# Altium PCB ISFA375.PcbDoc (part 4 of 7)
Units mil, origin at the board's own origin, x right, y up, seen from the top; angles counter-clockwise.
Board outline 5615 x 5520 mil, 6 copper layers (Top_SL, GND, POWER, Signal_Layer, GND2, Bottom_SL), stack 60.472 mil thick; 494 components, 307 nets, 1648 pads, 755 vias.
Unrouted connection lines stored in the file: 315.
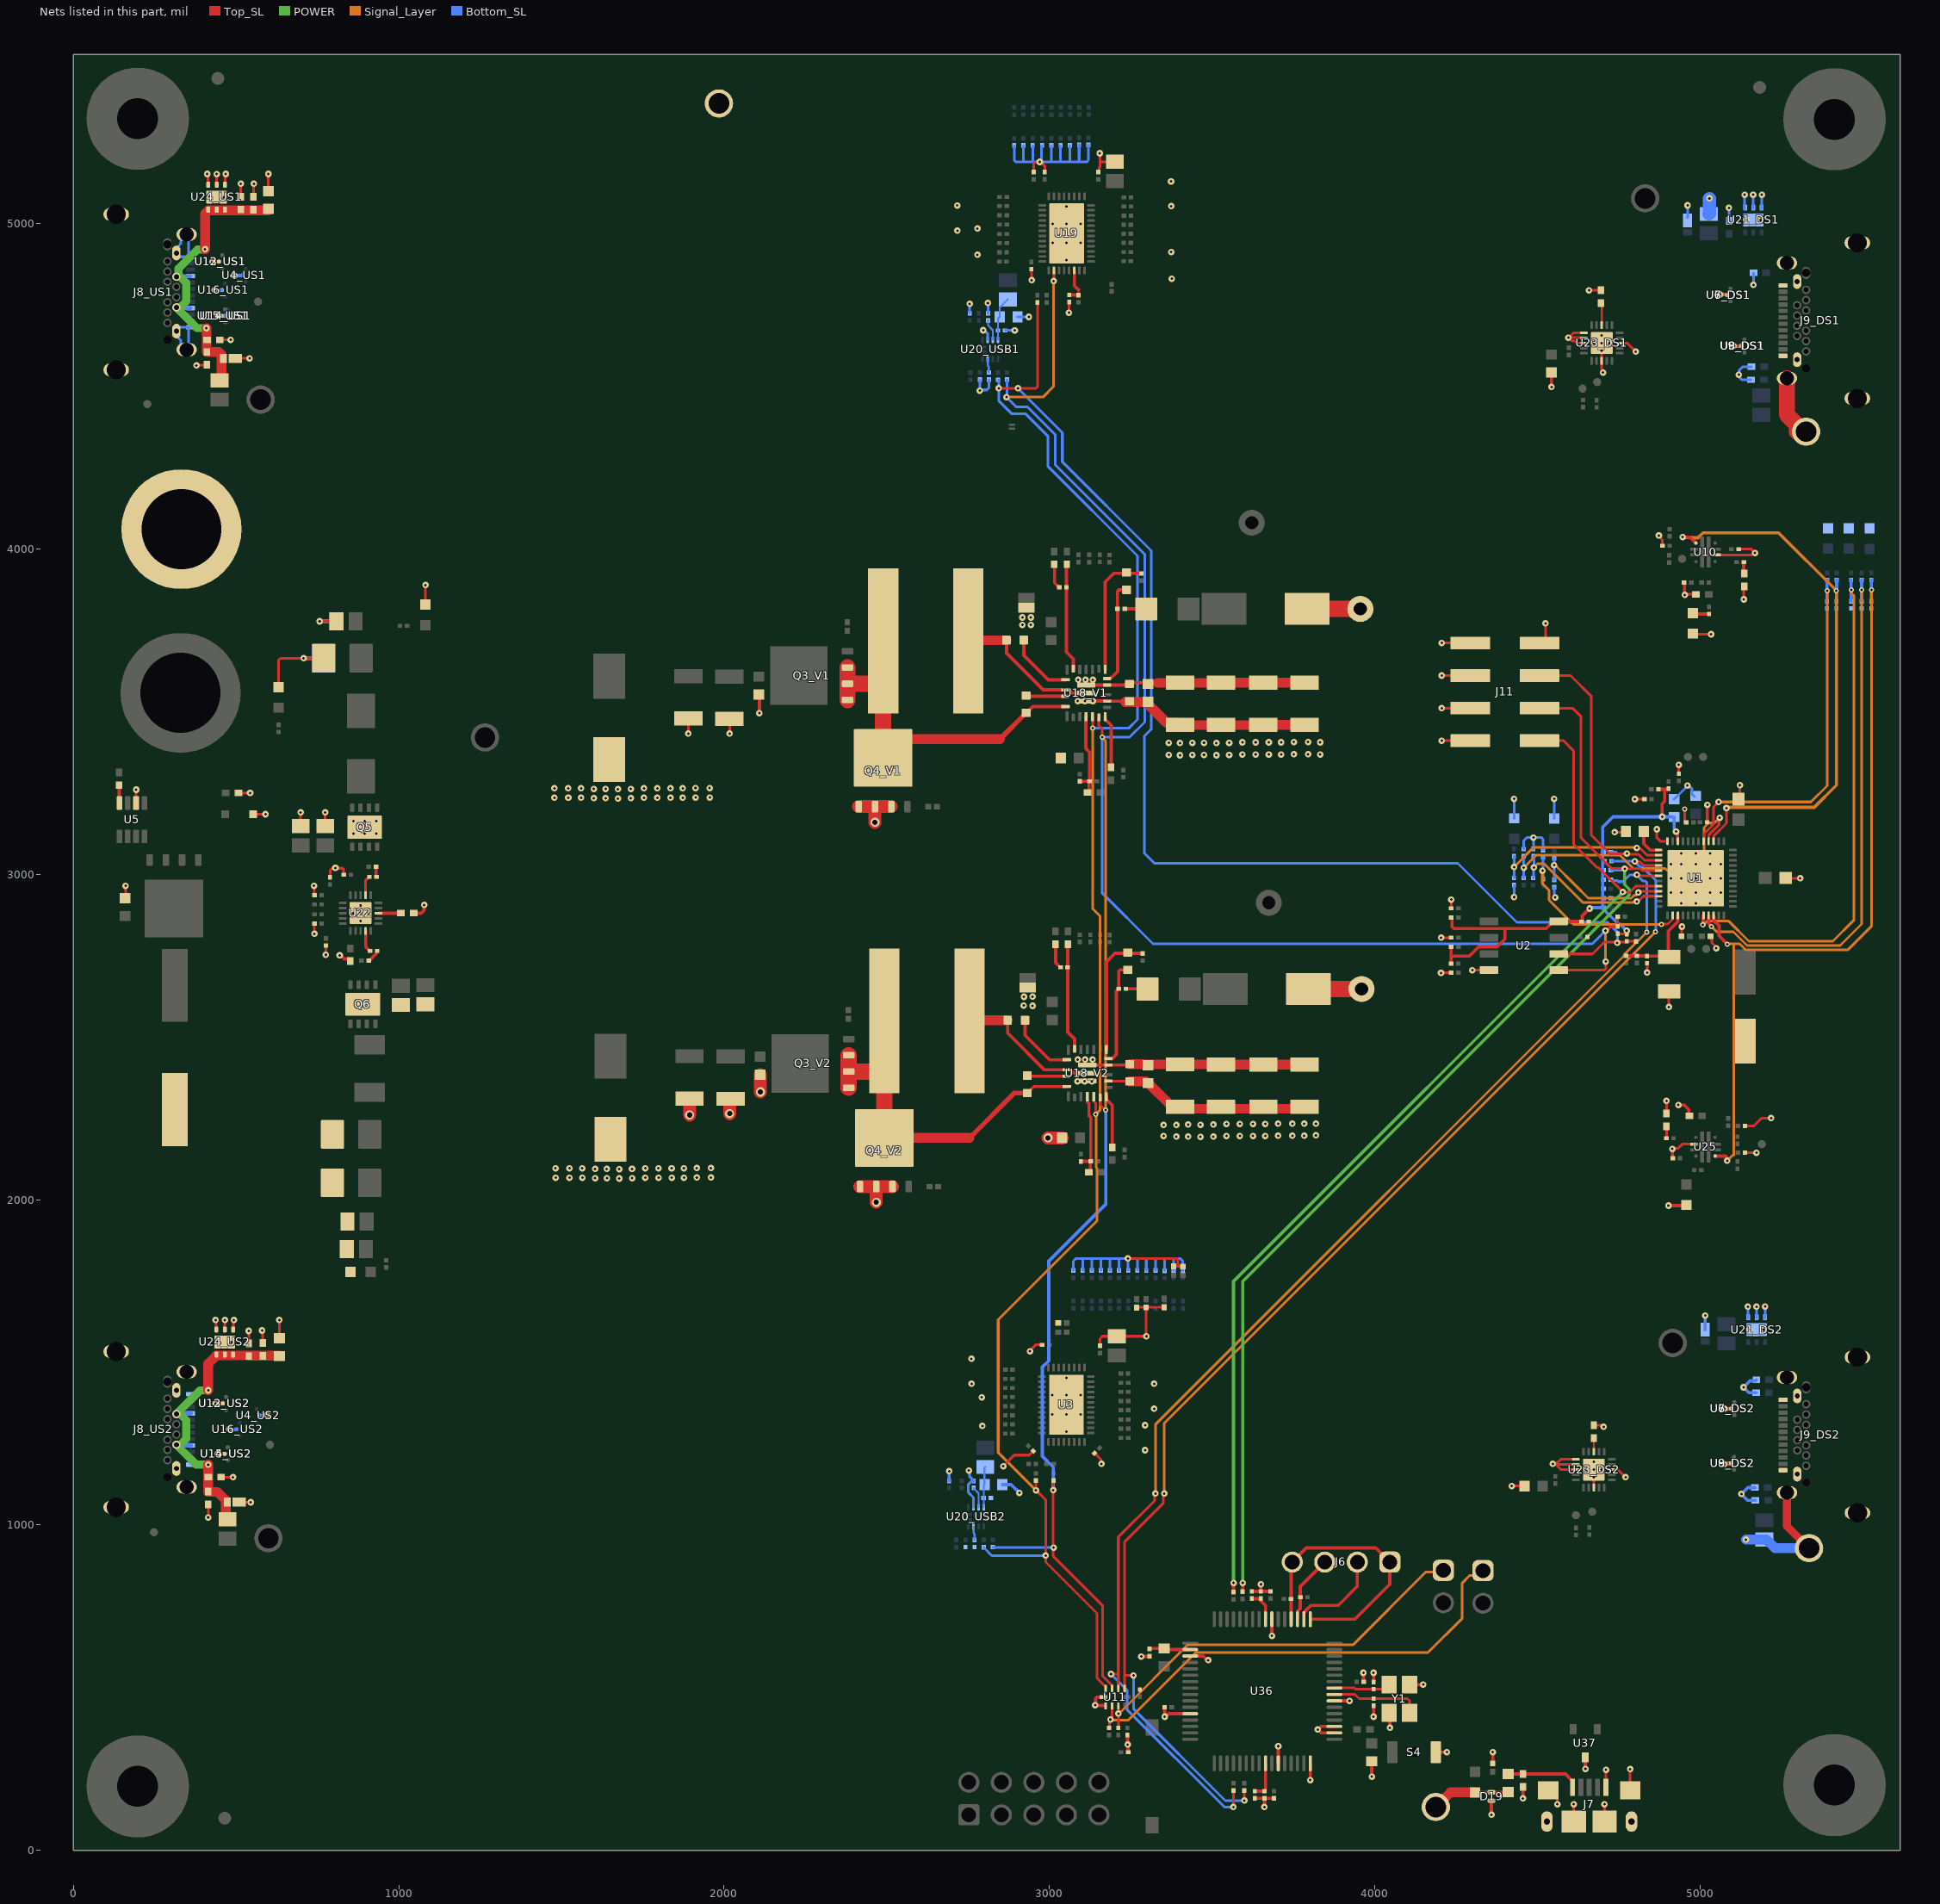
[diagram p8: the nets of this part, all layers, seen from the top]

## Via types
v1: diameter 20, hole 8, Top_SL to Bottom_SL, 628 vias
v2: diameter 19.68, hole 7.87, Top_SL to Bottom_SL, 66 vias
v3: diameter 16, hole 8, Top_SL to Bottom_SL, 23 vias
v4: diameter 16, hole 6, Top_SL to Bottom_SL, tented both sides, 16 vias
v5: diameter 137.8, hole 125.98, Top_SL to Bottom_SL, 8 vias
v6: diameter 50, hole 28, Top_SL to Bottom_SL, 8 vias
v7: diameter 28, hole 16, Top_SL to Bottom_SL, 6 vias

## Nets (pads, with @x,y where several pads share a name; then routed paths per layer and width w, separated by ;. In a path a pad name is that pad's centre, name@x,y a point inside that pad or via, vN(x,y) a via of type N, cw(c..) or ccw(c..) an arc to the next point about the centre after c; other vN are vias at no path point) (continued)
GND: C1.1 C2.1 C3.2 C4.2 C5.2 C6.2 C7.2 C8.1 C9.1 C10.2 C11.2 C12.2 C13.2 C14.2 C15.2 C16.2 C17.2 C20.2 C23.2 C36.2 C37.1 C40_V1.2 C40_V2.2 C41_V1.2 C41_V2.2 C42_V1.2 C42_V2.2 C43_V1.2 C43_V2.2 C45_V1.2 C45_V2.2 C47_V1.2 C47_V2.2 C48_V1.2 C48_V2.2 C49_V1.2 C49_V2.2 C50_V1.2 C50_V2.2 C51_V1.2 C51_V2.2 C52_V1.2 C52_V2.2 C59.2 C60.2 C61.2 C62.2 C63.2 C65.2 C66.2 C80_V1.1 C80_V2.1 C82_USB1.2 C82_USB2.2 C83_USB1.2 C83_USB2.2 C84.1 C85_USB1.2 C85_USB2.2 C86.2 C88_DS1.1 C88_DS2.1 C90.2 C91.2 C92.2 C93.2 C94.2 C95.2 C96.2 C97.2 C98.2 C99.2 C100_USB1.2 C100_USB2.2 C101.2 C102.2 C103.2 C105.2 C106.2 C107.2 C108.2 C109_US1.2 C109_US2.2 C110.2 C111_US1.2 C111_US2.2 C112.2 C113.2 C114.2 C115.1 C116.2 C118_DS1.2 C118_DS2.2 C119_DS1.2 C119_DS2.2 C120_DS1.2 C120_DS2.2 C121_DS1.2 C121_DS2.2 C122_DS1.2 C122_DS2.2 C123_DS1.1 C123_DS2.1 C124_US1.2 C124_US2.2 C125_US1.2 C125_US2.2 C126_US1.2 C126_US2.2 C127.2 C128.2 C129.1 C130.1 C131.1 D1.1 D2.1 D9.1 D10.1 D11.1 D12.1 D13_DS1.2 D13_DS2.2 D14_US1.2 D14_US2.2 D15.1 D16.1 D17.1 D18.1 D19.1 D21.1 J7.5 J7.6 J7.7 J7.8 J7.9 J7.10 J7.11 J8_US1.1 J8_US1.2 J8_US1.3 J8_US1.4 J8_US1.A1 J8_US1.A12 J8_US1.B1 J8_US1.B12 J8_US2.1 J8_US2.2 J8_US2.3 J8_US2.4 J8_US2.A1 J8_US2.A12 J8_US2.B1 J8_US2.B12 J9_DS1.1 J9_DS1.2 J9_DS1.3 J9_DS1.4 J9_DS1.A1 J9_DS1.A12 J9_DS1.B1 J9_DS1.B12 J9_DS2.1 J9_DS2.2 J9_DS2.3 J9_DS2.4 J9_DS2.A1 J9_DS2.A12 J9_DS2.B1 J9_DS2.B12 J11.2 J11.4 J11.6 J11.7 J11.8 J15.1 NT1_V1.1 NT1_V2.1 Q4_V1.1 Q4_V1.2 Q4_V1.3 Q4_V2.1 Q4_V2.2 Q4_V2.3 Q5.9@895.11,3145.01 Q6.9@889.16,2600.69 R12.1 R20.1 R21.1 R24.1 R25.1 R26.1 R27.1 R28.1 R31.2 R32.2 R51.1 R52.1 R53.1 R54.1 R55.1 R56.1 R57.1 R58.1 R59.1 R60.1 R61.1 R64.1 R91_USB1.2 R91_USB2.2 R92.2 R93.1 R94.1 R95.1 R96.1 R97.1 R98.1 R99.1 R100.1 R101.1 R102.2 R104_USB1.1 R104_USB2.1 R107.2 R111.1 R112.1 R113.1 R123.1 R124.1 R130.2 R131.2 R132.2 R134.1 R136.2 R137.2 R138.2 R139.1 R161.1 R162.1 R165.2 R167.1 R170.2 R171.1 S4.1 TP6.1 TP8_V1.1 TP8_V2.1 TP11_DS1.1 TP11_DS2.1 U1.36 U1.49 U2.4 U3.41 U4_US1.1@519.08,4841 U4_US2.1@572.72,1336.58 U5.2 U6_DS1.1@5083.33,4781.01 U6_DS2.1@5095.54,1357.5 U7_DS1.1@5083.42,4780.98 U7_DS2.1@5096.08,1358 U8_DS1.1@5126.91,4624.27 U8_DS2.1@5095.08,1190 U9_DS1.1@5126.61,4623.98 U9_DS2.1@5095.08,1190 U10.8 U11.5 U11.6 U12_US1.1@447.16,4883.32 U12_US2.1@459.08,1374 U13_US1.1@447.16,4883.32 U13_US2.1@459.06,1373.75 U14_US1.1@463.62,4716.48 U14_US2.1@463.98,1218.66 U15_US1.1@455.59,4717.18 U15_US2.1@465.08,1219 U16_US1.1@456,4796 U16_US2.1@500.63,1294 U18_V1.9 U18_V1.24 U18_V2.9 U18_V2.24 U19.41 U20_USB1.10 U20_USB2.10 U21_DS1.1 U21_DS1.2 U21_DS1.3 U21_DS1.7@5164,5011.61 U21_DS2.1 U21_DS2.2 U21_DS2.3 U21_DS2.7@5174,1600.61 U22.21@882.47,2880.95 U23_DS1.6 U23_DS1.7 U23_DS1.8 U23_DS1.13 U23_DS1.18 U23_DS1.21@4697.97,4633.37 U23_DS2.6 U23_DS2.7 U23_DS2.8 U23_DS2.13 U23_DS2.18 U23_DS2.21@4673.68,1170.32 U24_US1.1 U24_US1.2 U24_US1.3 U24_US1.7@440,5081.61 U24_US2.1 U24_US2.2 U24_US2.3 U24_US2.7@465,1562.61 U25.8 U36.3 U36.12 U36.27 U36.32 U36.34 U36.35 U36.39 U36.55 U37.3 Y1.2 Y1.4 | length 13672.6
  Top_SL w8: C103.2@158.92,2927.2 159.89,2928.17 v1(159.89,2965.02) ; U5.2@192.39,3219.42 v1(192.39,3260.5) ; v1(377.62,4564.47) 378.6,4565.46 409.32,4565.46 C124_US1.2@410.3,4566.44 ; v1(411,5153) 412.7,5151.3 412.7,5121.7 U24_US1.3@414.41,5120 ; v1(413.9,1023.38) 414.15,1023.62 414.15,1063.38 C124_US2.2@414.39,1063.62 ; v1(426.63,4882.57) U13_US1.1@446.6,4882.57 ; v1(437,1630) 438.2,1628.8 438.2,1599.41 U24_US2.3@439.44,1598.17 ; U24_US1.2@440,5120 v1@440,5152.78 ; v1(441.47,4718.12) 441.94,4717.65 455.12,4717.65 U15_US1.1@455.59,4717.18 ; C111_US1.2@449.69,4643 449.86,4643.17 482.65,4643.17 v1(482.82,4643.35) ; C111_US2.2@453.69,1147 453.86,1147.17 490.45,1147.17 v1(490.63,1147.35) ; U24_US2.2@465.03,1598.17 v1(465.03,1630.17) ; U24_US1.1@465.59,5117.77 466.8,5118.98 466.8,5151.8 v1(468,5153) ; U24_US2.1@490.63,1598.17 491.8,1599.34 491.8,1628.8 v1(493,1630) ; D14_US1.2@498.7,4586.13 v1(541.19,4586.13) ; D14_US2.2@503.52,1070 v1(544.38,1070) ; C102.2@506.69,3250 v1(543,3250) ; C126_US1.2@514,5083.32 v1(514,5122.95) ; C126_US2.2@538.77,1563.86 v1(538.77,1596.75) ; D9.1@552.31,3185.39 552.5,3185.19 589.81,3185.19 v1(590,3185) ; C125_US1.2@553,5082.69 553.89,5083.58 553.89,5122.06 v1(554.79,5122.95) ; v1(579.83,1598.17) 580.91,1597.09 580.91,1560.77 C125_US2.2@582,1559.69 ; C109_US1.2@599,5100.56 v1(599,5153) ; D10.1@630,3575.46 630,3657.88 636.5,3664.38 v1(707.49,3664.38) ; v1(632.77,1630.17) 632.77,1574.79 C109_US2.2@633,1574.56 ; v1(698.11,3190.47) 698.11,3148.84 C66.2@698.61,3148.34 ; v1(739.21,2965.02) 739.94,2964.29 739.94,2936.8 R112.1@740.68,2936.06 ; R111.1@740.59,2849.03 R111.1@740.59,2849.03 740.63,2817.49 v1(740.68,2817.45) ; C90.2@768.5,3664.38 C90.2@769.12,3665 ; v1(773.59,3190.47) 773.59,3148.5 C65.2@773.75,3148.34 ; v1(775.83,2752.88) R113.1@775.83,2781.15 ; R28.1@788.77,2991.22 788.77,3011.8 794.66,3017.69 802.77,3017.69 v1(805.07,3019.99) 806.14,3018.92 827.07,3018.92 830.69,3015.3 R24.1@830.69,2999.09 ; D11.1@1082.02,3829.18 1082.21,3829.37 v1(1082.21,3889.38) ; v1(1890.13,3432.62) C40_V1.2@1890.13,3479.21 ; C41_V1.2@2016.13,3478.21 2017.13,3477.21 v1(2017.13,3432.62) ; v1(2857.88,1181.02) 2891.81,1214.95 2937.6,1214.95 2950.29,1227.64 C16.2@2950.79,1227.64 ; v1(2940.42,1534.01) 2940.42,1536.9 2957.36,1553.84 C14.2@2977.7,1553.84 ; C62.2@2944.65,4860.67 2944.94,4860.38 2944.94,4826.92 v1(2945.24,4826.62) ; C60.2@2951.5,5158.71 2951.5,5185.28 2954.45,5188.23 2968.5,5188.23 v1(2970.31,5190.04) ; v1@2971.16,5188.23 2973.46,5190.53 2973.46,5189.97 2985.63,5177.8 C61.2@2985.63,5158.71 ; v1(3059.73,4726.4) 3060.28,4726.96 3060.28,4758.59 C84.1@3060.84,4759.15 ; C17.2@3138.85,1221.29 3157.71,1202.43 3157.71,1190.2 v1(3160.01,1187.9) ; C63.2@3150.01,5158.71 3152.31,5161.01 3152.31,5171.3 3155.73,5174.72 3155.73,5190.53 ; v1(3154.38,5216.65) 3155.73,5215.3 3155.73,5190.53 ; C15.2@3155.61,1550.69 3155.61,1573 3162.83,1580.22 C13.2@3207.1,1580.22 v1(3298.14,1580.22) 3297.57,1580.79 3297.57,1668.44 R60.1@3297,1669.01 ; U18_V2.9@3181.12,2364.75 3181.78,2364.09 C80_V2.1@3246.34,2364.09 ; C59.2@3201.31,5190.53 3155.73,5190.53 ; v1(3241.08,1819.49) 3391.81,1819.49 3394.54,1816.76 3394.54,1795.15 ; R54.1@3268.21,1668.5 3268.96,1669.25 3352.25,1669.25 R56.1@3353,1670.01 ; R59.1@3382.07,1795.7 3382.61,1795.15 3394.54,1795.15 ; R57.1@3410.14,1794.61 3409.6,1795.15 3394.54,1795.15 ; v1(4203.78,2696.83) 4204.3,2697.35 4234.46,2697.35 R27.1@4234.98,2697.87 ; v1(4204,2805.51) R26.1@4235.19,2805.52 ; v1(4205.91,3411.17) J11.2@4293.85,3411.17 ; v1(4205.91,3511.17) J11.4@4293.85,3511.17 ; v1(4205.91,3611.17) J11.6@4293.85,3611.17 ; v1(4205.91,3711.17) J11.8@4293.85,3711.17 ; R25.1@4235.19,2895.57 v1(4235.19,2922.43) ; v1(4300.25,2705.52) U2.4@4350.93,2705.52 ; v1(4420.99,1119.81) C122_DS2.2@4460.77,1119.81 ; J11.7@4506.44,3711.17 4509.1,3711.17 4524.79,3726.85 v1(4524.79,3771.62) ; J7.8@4533.33,185 4537.27,185 4560.83,161.45 4560.83,142.34 v1(4561.47,141.7) ; v1(4547.78,1188.19) 4549.84,1186.13 v1@4557.03,1186.13 ; v1@4554.97,1188.19 4558.22,1188.19 4571.84,1201.82 U23_DS2.6@4618.56,1201.82 ; v1(4595.31,4649.73) 4637.93,4649.73 4637.93,4649.6 4638.41,4649.12 U23_DS1.7@4642.85,4649.12 ; v1@4599.23,4645.81 4599.35,4645.93 4606,4639.28 4615.65,4639.28 4621.55,4633.37 U23_DS1.8@4642.85,4633.37 ; v1@4599.65,4650.39 4599.65,4653.23 4611.29,4664.87 U23_DS1.6@4642.85,4664.87 ; J7.10@4612.06,88.56 v1(4612.06,141.7) ; U23_DS2.8@4618.56,1170.32 4572.84,1170.32 v1@4557.03,1186.13 ; U23_DS2.7@4618.56,1186.07 4618.5,1186.13 v1@4557.03,1186.13 ; v1(4658.88,4795.28) v1(4658.88,4795.28) 4695.94,4795.33 C123_DS1.1@4696,4795.39 ; U23_DS2.13@4673.68,1115.2 v2(4673.68,1146.7) ; C123_DS2.1@4673.68,1306.95 4674.16,1307.43 4694.88,1307.43 4700.56,1301.75 v1(4703.81,1301.75) ; v2(4697.97,4609.75) U23_DS1.13@4697.97,4578.25 4697.97,4552.83 4699.29,4551.51 4699.29,4544.91 v1(4701.58,4542.62) ; J7.11@4706.56,88.55 v1(4706.56,141.7) ; J7.5@4710.5,193.86 4710.75,194.11 4710.75,247.75 v1(4711,248) ; U23_DS2.18@4728.8,1170.32 4747.89,1170.32 v1(4771.23,1146.98) ; v1(4737.66,3130) 4770.3,3130 C9.1@4772.34,3132.03 ; U23_DS1.18@4753.09,4633.37 4775.82,4633.37 v1(4802.39,4606.8) ; v1(4785,250) 4785,185.31 J7.9@4785.3,185 ; v1(4799.91,3231.26) 4800.06,3231.41 4828.69,3231.41 R21.1@4828.84,3231.56 ; R132.2@4837.31,2726.96 4837.49,2726.78 4837.49,2698.22 v1(4837.67,2698.04) ; v1(4867.5,3138.63) 4867.5,3112.72 4878.05,3102.17 U1.36@4900.39,3102.17 ; v1(4873.45,4041.64) 4873.45,4039.22 4884.27,4028.4 4884.27,4012.4 4884.55,4012.11 R107.2@4884.55,4010.1 ; v1(4896.83,2304) 4897.17,2303.66 C131.1@4897.17,2264.63 ; v1(4904.35,2592.59) 4904.35,2639.85 C129.1@4904.75,2640.25 ; v1(4914.75,2156.09) 4917.05,2158.39 4932.81,2158.39 4945.28,2170.86 U25.8@4981.41,2170.86 ; R12.1@4934.92,3309.24 v1(4934.92,3337) ; C6.2@4943.02,2810 4943.95,2810.93 4943.95,2838.66 v1(4944.88,2839.59) ; R64.1@4951.31,3896.96 4952.23,3896.03 4952.23,3860.17 v1(4953.16,3859.24) ; v1@4951.4,3861 C3.2@4987.85,3861 ; v3(4952.95,3201.2) 4953.06,3201.1 4953.06,3160.73 C1.1@4953.16,3160.63 ; D1.1@4978.29,3740.13 4980.26,3738.16 v1(5033.98,3738.16) ; C2.1@5021.92,3160.63 5022.38,3161.09 5022.38,3213.32 v1(5022.84,3213.78) ; C7.2@5031.99,2810 5032.25,2810 5036.51,2805.73 5036.51,2789.73 5050,2776.25 v1(5050,2773) ; U10.8@5052.36,3982.05 5159.98,3982.05 5165.93,3988 v1(5169.18,3988) 5157.41,3999.76 R139.1@5118.7,3999.76 ; C86.2@5117.26,3213.78 5118.51,3215.03 5118.51,3241.08 5122.44,3245.01 v1(5122.44,3274.3) ; C130.1@5133.4,3883.22 5134.13,3882.5 5134.13,3846.18 v1(5134.85,3845.45) ; R170.2@5138.1,2144.45 v1(5173.61,2144.45) ; R167.1@5138.28,2226.45 5141.17,2226.45 5141.37,2226.24 5164.78,2226.24 5189.38,2250.85 v1(5218.47,2250.85) ; C11.2@5263.36,2988.87 5264.23,2988 v1(5308,2988)
  Top_SL w10: v1(436.72,1373.75) U13_US2.1@459.06,1373.75 ; v1(442.84,1219.18) 442.93,1219.09 464.99,1219.09 U15_US2.1@465.08,1219 ; v1(707.49,3664.38) C90.2@768.5,3664.38 ; v1(756.75,3778) C95.2@808.01,3778 ; v1(818.3,2751.31) 821,2751.31 832.3,2740.01 845.73,2740.01 850.57,2735.17 C98.2@850.57,2733.2 ; C99.2@1045.98,2880.95 1069.22,2880.95 1077.75,2889.47 v1(1077.75,2906.22) ; C42_V1.2@2107.13,3552.61 2108.53,3551.21 v1(2108.53,3495.76) ; U18_V1.24@3112.86,3532.75 3132.83,3532.75 v1(3133.08,3533) 3133.33,3532.75 U18_V1.9@3177.33,3532.75 ; U11.5@3166.57,470.96 3146.27,470.96 3142.32,467.01 3142.32,448.39 v1(3140.41,446.48) 3141.46,445.43 3171.43,445.43 U11.6@3172.48,444.38 ; U18_V1.9@3184.63,3532.67 3230.39,3532.67 ; R162.1@3239.85,354.55 3240.24,354.15 3240.24,325.89 v1(3240.64,325.5) 3241.37,324.76 3241.37,302.29 R161.1@3242.11,301.56 ; v1(3282.12,595.77) 3282.81,596.46 3306.95,596.46 C37.1@3307.64,597.15 ; C107.2@3354.27,439.98 v1(3354.27,410.87) 3356.98,410.87 3366.41,420.3 U36.12@3432.9,420.3 ; U36.3@3432.9,597.46 3472.51,597.46 3485.42,584.55 v1(3488,584.55) ; C110.2@3622,796.02 3622.07,795.95 C128.2@3650.03,795.95 ; C108.2@3631.33,160.03 C127.2@3660.86,160.03 ; C128.2@3650.03,795.89 C128.2@3650.03,795.95 ; v1(3650.03,817.9) C128.2@3650.03,795.95 ; v1(3660.86,133.36) C127.2@3660.86,160.03 ; C105.2@3679.56,795.89 3679.49,795.95 C128.2@3650.03,795.95 ; v1(3683.89,659.45) U36.55@3683.89,710.65 ; C106.2@3690.21,159.23 C106.2@3690.21,160.02 ; C106.2@3690.21,160.02 C127.2@3660.86,160.03 ; U36.27@3703.57,267.74 v1(3703.57,320.26) ; v1(3802,215.74) U36.32@3802,267.74 ; v1(3824.85,371.66) v1@3825.79,371.66 ; U36.34@3875.82,361.24 3836.21,361.24 v1@3825.79,371.66 ; U36.35@3875.82,380.93 3836.21,380.93 3826.94,371.66 v1@3825.79,371.66 ; U36.39@3875.82,459.67 v1@3922.55,459.69 ; v1(3965.32,545.89) 3965.88,545.32 3965.88,518.88 C36.2@3966.44,518.32 C36.2@3966.25,518.12 ; v1(3990.85,226.65) C112.2@3990.85,274 ; v1@3996.5,410.87 C113.2@3996.52,444.31 ; C114.2@3996.52,517.67 v1(3996.45,545.89) ; Y1.4@4044.5,423.05 4046.48,421.07 v1(4046.48,376.64) ; Y1.2@4107.5,509.67 v1(4149,509.67) ; S4.1@4187.94,301.56 4188.38,302 v1(4222,302) ; v1(4358.86,109.26) D19.1@4358.86,153.04 ; R134.1@4362.92,267.31 4363.04,267.44 4363.04,301.88 v1(4363.17,302) ; v1(4455.86,159.83) C115.1@4455.86,195.15 ; v1(4543.49,4498.34) C122_DS1.2@4543.49,4542.62 ; U37.3@4647.1,285.81 4647.46,285.45 4647.46,250.9 v1(4647.82,250.54) ; v1(4902.75,1981.92) 4955.99,1981.92 D2.1@4957.96,1983.89 ; v1(4914.75,2156.09) 4915.44,2155.41 4915.44,2128.24 R171.1@4916.13,2127.55 ; v1(4933.62,2291) 4951.71,2291 4965.6,2277.12 4965.6,2259.62 C5.2@4967.08,2258.13 ; v1(5061.44,4782.41) 5062.14,4781.71 5082.63,4781.71 U6_DS1.1@5083.33,4781.01 ; v1(5074,1187.07) 5076.71,1187.07 5078.73,1189.09 5094.17,1189.09 U8_DS2.1@5095.08,1190 ; v1(5074.66,1357.63) 5095.42,1357.63 U6_DS2.1@5095.54,1357.5 ; v1(5103.55,4623.98) 5103.69,4624.12 5126.76,4624.12 U8_DS1.1@5126.91,4624.27
  Top_SL w25: J9_DS2.1@5267.46,1099.6 5267.46,996.57 TP11_DS2.1@5335.13,928.9
  Top_SL w30: C80_V1.1@3233.42,3529.8 3296.63,3529.8 3360.11,3466.32 3394.18,3466.32 3401.58,3458.92 C50_V1.2@3657.47,3458.92 ; C80_V2.1@3247,2363.43 3297.03,2363.43 3302.02,2358.44 3303.98,2358.44 3369.72,2292.7 3394.98,2292.7 3407.82,2279.87 3521.75,2279.87 C49_V2.2@3527.65,2285.77 3533.66,2279.77 3651.63,2279.77 C50_V2.2@3657.53,2285.67 3663.44,2279.77 3778.63,2279.77 C51_V2.2@3784.53,2285.67 ; C50_V1.2@3657.47,3459.29 C51_V1.2@3784.47,3459.29
  Top_SL w40: v7(1893.91,2260.48) C40_V2.2@1893.91,2311.21 ; v7(2017.13,2264.62) 2017.13,2308.55 2018.78,2310.21 C41_V2.2@2019.91,2310.21 ; C42_V2.2@2110.91,2384.61 2110.91,2332.03 v7(2111.66,2331.28) ; Q4_V1.1@2413.83,3208.4 Q4_V1.2@2463.83,3208.4 ; Q4_V2.1@2417.62,2040.4 Q4_V2.2@2467.62,2040.4 ; v7(2463.83,3160.17) Q4_V1.2@2463.83,3208.4 ; v7(2467.62,1992.17) Q4_V2.2@2467.62,2040.4 ; Q4_V1.3@2513.83,3208.4 Q4_V1.2@2463.83,3208.4 ; Q4_V2.3@2517.62,2040.4 Q4_V2.2@2467.62,2040.4 ; v7(2995.91,2190.01) C45_V2.2@3038.83,2190.01
  Top_SL w50: J15.1@331.92,4061.16 J15.1@418.26,4061.16 ; C52_V1.2@3792.69,3815.9 TP8_V1.1@3955.74,3815.9 ; C52_V2.2@3796.48,2647.9 TP8_V2.1@3959.53,2647.9 ; J9_DS1.1@5267.11,4525.1 5267.11,4412.71 5298.01,4381.81 TP11_DS1.1@5298.01,4360.98
  Bottom_SL w8: J8_US1.A1@359.92,4681.73 J8_US1.A1@356.71,4681.73 ; J8_US1.A12@359.92,4898.27 J8_US1.A12@356.71,4898.27 ; v1(426.63,4882.57) U12_US1.1@446.41,4882.57 ; v1(434,4795.9) 434.05,4795.95 455.95,4795.95 U16_US1.1@456,4796 ; v1(441.47,4718.12) 442.29,4717.3 462.8,4717.3 U14_US1.1@463.42,4716.69 ; v1(2752.24,1167.42) 2754.15,1165.51 2754.15,1149.86 2767.27,1136.74 C100_USB2.2@2767.27,1135.95 2767.27,1135.16 2765.97,1133.86 2759.71,1133.86 2750.97,1125.13 2750.97,1100.06 2766.56,1084.48 U20_USB2.10@2766.56,1054.57 ; R104_USB1.1@2755,4725.02 v1(2755,4753.49) ; v1(2785.81,4487) v1@2785.9,4487.1 ; R91_USB1.2@2786,4520.98 2785.9,4520.88 v1@2785.9,4487.1 ; v1(2796.43,4672.57) 2799.68,4672.57 2808.51,4663.74 2810.55,4663.74 U20_USB1.10@2810.55,4643.27 ; v1(2810.82,4756.6) 2811.04,4756.38 2811.04,4724.87 C100_USB1.2@2811.27,4724.65 ; C85_USB1.2@2814,4520.98 2814,4495.7 2807.6,4489.3 2788.1,4489.3 v1@2785.9,4487.1 ; C82_USB1.2@2864.02,4672 v1(2893.5,4672) ; R94.1@2891.67,5240.65 2891.67,5195.21 2896.36,5190.53 2919.24,5190.53 ; C83_USB1.2@2902.11,4713.62 v1(2936.93,4713.62) ; R101.1@2920.21,5240.65 2920.21,5191.49 2919.24,5190.53 ; R99.1@2948.74,5240.65 2948.74,5191.21 2948.06,5190.53 ; v1(2970.31,5190.04) 2969.82,5190.53 2948.06,5190.53 ; R93.1@2977.28,5240.64 2975.37,5238.73 2975.37,5192.44 2973.46,5190.53 3003.9,5190.53 ; R100.1@3005.81,5240.64 3005.81,5192.44 3003.9,5190.53 ; R96.1@3034.35,5240.64 3034.35,5190.53 ; R98.1@3062.88,5240.64 3062.88,5190.53 ; R53.1@3073.26,1782.44 3073.26,1810.96 3081.78,1819.49 3213.63,1819.49 ; R95.1@3091.42,5242.64 3091.42,5190.53 ; R52.1@3102.14,1782.62 3102.45,1782.92 3102.45,1819.49 ; R97.1@3119.95,5242.64 3119.95,5195.21 3115.27,5190.53 3091.42,5190.53 ; R124.1@3130.14,1782.44 3130.14,1819.49 ; R61.1@3158.14,1782.62 3158.14,1819.49 ; R58.1@3186.14,1782.63 3186.14,1819.49 ; R51.1@3214.11,1782.72 3214.11,1819.01 3213.63,1819.49 ; R55.1@3242.14,1782.89 v1@3242.11,1810.96 ; R54.1@3270.14,1782.89 3270.14,1819.49 ; R60.1@3298.14,1781.89 3297.85,1782.18 3297.85,1819.49 ; R123.1@3326.14,1782.62 3326.14,1819.49 ; R56.1@3354.14,1781.62 3354.14,1819.49 ; R59.1@3382.14,1782.63 3382.07,1782.71 3382.07,1819.49 ; R57.1@3410.14,1781.62 3410.14,1810.96 3401.62,1819.49 3382.07,1819.49 ; v1(4428.35,2930.21) R32.2@4428.35,2966.99 ; D16.1@4428.35,3172.38 v1(4428.35,3232.01) ; R102.2@4458.22,3077.65 4458.22,3104.36 4467,3113.14 v1(4488.14,3113.14) ; R131.2@4487.98,3078.2 4488.06,3078.28 v1(4488.14,3113.14) v1(4488.14,3113.14) ; R130.2@4517.7,3074.87 4517.7,3107.91 4512.48,3113.14 v1(4488.14,3113.14) ; v1(4551.57,3232.01) 4551.57,3172.69 D15.1@4552,3172.26 ; R31.2@4552,2961.03 4552,2935.25 4555,2932.25 v1(4555,2929) ; C8.1@4920.5,3231.56 4932.25,3243.31 4933.23,3243.31 4961.02,3271.1 v1(4961.02,3273.06) ; D13_DS1.2@4961.04,5018.82 4962,5019.78 v1(4962,5056.5) ; v1@4965,3273.06 4975.81,3262.25 4975.81,3246.14 C4.2@4982.76,3239.19 ; v1(5088.96,5048.72) 5089.59,5048.09 5089.59,5008.9 C119_DS1.2@5090.22,5008.27 ; v1(5137,5089) 5137.41,5088.59 5137.41,5046.18 U21_DS1.1@5137.82,5045.77 ; v1(5147.32,1671.05) 5147.66,1670.7 5147.66,1636.11 U21_DS2.1@5148,1635.77 ; C120_DS1.2@5156.52,4520.5 5128.49,4520.5 5121.53,4527.46 5121.53,4533.43 v1(5119.23,4535.73) 5120.43,4536.93 5120.43,4549.64 5131.3,4560.51 C121_DS1.2@5158.25,4560.51 ; U21_DS1.2@5163.41,5045.77 v1(5163.41,5089) ; v1(5164.16,4812.18) C118_DS1.2@5164.16,4848.92 ; U21_DS2.2@5173.6,1635.78 v1(5173.61,1671.05) ; U21_DS1.3@5189,5045.77 5189.5,5046.27 5189.5,5088.5 v1(5190,5089) ; U21_DS2.3@5199.25,1635.84 5199.8,1636.39 5199.8,1671.8 v1(5200,1672) ; J8_US1.A1@356.71,4681.73 324.35,4681.73 316.22,4673.61 J8_US1.B12@316.22,4669.92 316.22,4655.32 329.9,4641.64 329.9,4627.33 344.39,4612.83 J8_US1.1@347.72,4612.83 353.82,4618.94 353.82,4678.84 J8_US1.A1@356.71,4681.73 ; J8_US1.A12@356.71,4898.27 324.35,4898.27 316.22,4906.39 J8_US1.B1@316.22,4910.08 316.22,4924.68 329.9,4938.36 329.9,4952.67 344.39,4967.17 J8_US1.2@347.72,4967.17 353.82,4961.06 353.82,4901.16 J8_US1.A12@356.71,4898.27 ; 2919.24,5190.53 2948.06,5190.53 ; 3003.9,5190.53 3034.35,5190.53 ; 3034.35,5190.53 3062.88,5190.53 ; 3062.88,5190.53 3091.42,5190.53 ; 3213.63,1819.49 v1(3241.08,1819.49) 3270.14,1819.49 ; 3270.14,1819.49 3297.85,1819.49 ; 3297.85,1819.49 3326.14,1819.49 ; 3326.14,1819.49 3354.14,1819.49 ; 3354.14,1819.49 3382.07,1819.49
  Bottom_SL w10: v1(436.72,1373.75) 436.85,1373.88 458.95,1373.88 U12_US2.1@459.08,1374 ; v1(442.84,1219.18) 443.1,1218.92 463.72,1218.92 U14_US2.1@463.98,1218.66 ; v1(478.81,1295.03) 479.32,1294.51 500.11,1294.51 U16_US2.1@500.63,1294 ; v1(494.14,4840.05) 494.61,4840.53 518.6,4840.53 U4_US1.1@519.08,4841 ; U4_US2.1@572.72,1336.58 590.88,1336.58 592.29,1338 v1(595,1338) ; v1@706.86,3664.38 v1(707.49,3664.38) C91.2@768.5,3664.38 ; v1(756.75,3778) C94.2@808.01,3778 C94.2@805.55,3780.45 ; R104_USB2.1@2691.92,1135.95 v1(2691.92,1165.51) ; C83_USB2.2@2855.65,1124.12 2882.5,1124.12 v1(2907.71,1098.9) ; v1(3965.32,545.89) v1@3965.51,545.69 ; D13_DS2.2@5016,1600.83 v1(5016,1644.1) ; v1(5061.44,4782.41) 5062.16,4781.69 5082.7,4781.69 U7_DS1.1@5083.42,4780.98 ; v1(5074,1187.07) 5076.71,1187.07 5078.73,1189.09 5094.17,1189.09 U9_DS2.1@5095.08,1190 ; v1(5074.66,1357.63) 5074.85,1357.81 5095.89,1357.81 U7_DS2.1@5096.08,1358 ; v1(5103.55,4623.98) U9_DS1.1@5126.61,4623.98 ; C118_DS2.2@5168.43,1115.2 5146.93,1115.2 v1(5127.08,1095.35) 5146.43,1076 C119_DS2.2@5170.31,1076 ; C121_DS2.2@5172.31,1407 5150.17,1407 v1(5133.75,1423.42) 5153.39,1443.06 5170.37,1443.06 C120_DS2.2@5173.31,1446
  Bottom_SL w30: v1(5141.47,955.47) C88_DS2.1@5197.95,955.47 5203.86,955.47 5230.43,928.9 TP11_DS2.1@5335.13,928.9
  Bottom_SL w40: C88_DS1.1@5026.77,5029.92 5027.35,5029.92 5029,5031.58 v1(5029,5078)
  other v1: 3996.48,410.85 3922.57,459.71 3294,1230.22 2793.68,1304.52 3294,1307 3321.85,1357.76 2792.1,1392.66 2760.6,1434.26 3321.85,1434.26 2760.06,1511.04 1677.63,2065.25 1603.37,2066.11 1639.61,2066.11 1717.1,2066.11 1482.05,2067.81 1524.82,2067.81 1564.18,2067.81 1757.64,2067.81 1798.41,2067.81 1838.86,2067.81 1876.59,2067.81 1916.1,2068.48 1959.75,2068.48 1677.44,2094.13 1603.19,2094.99 1639.43,2094.99 1716.91,2094.99 1481.87,2096.69 1524.64,2096.69 1564,2096.69 1757.46,2096.69 1798.23,2096.69 1838.68,2096.69 1876.41,2096.69 1915.92,2097.37 1959.57,2097.37 3464.51,2193.18 3390.26,2194.04 3426.5,2194.04 3503.98,2194.04 3351.07,2195.74 3544.53,2195.74 3585.3,2195.74 3625.75,2195.74 3663.48,2195.74 3702.99,2196.41 3746.64,2196.41 3783.17,2196.46 3819.31,2198.12 3351.07,2229.77 3390.26,2229.77 3464.51,2230.38 3426.5,2231.24 3503.98,2231.24 3544.53,2232.94 3585.3,2232.94 3625.75,2232.94 3663.48,2232.94 3702.99,2233.62 3746.64,2233.62 3783.17,2233.66 3819.31,2233.62 3130.67,2363.43 3086.67,2364.09 3108.05,2364.09 2948,2596 2921,2597 2921.56,2623.86 2948,2624 860.08,3125.72 895.56,3125.72 931.03,3125.72 860.08,3164.3 895.56,3164.3 931.03,3164.3 1673.84,3233.25 1599.58,3234.11 1635.82,3234.11 1713.31,3234.11 1478.26,3235.81 1521.03,3235.81 1560.39,3235.81 1753.85,3235.81 1794.63,3235.81 1835.07,3235.81 1872.8,3235.81 1912.31,3236.48 1955.97,3236.48 1673.66,3262.13 1599.4,3262.99 1635.64,3262.99 1713.13,3262.99 1478.08,3264.69 1520.85,3264.69 1560.21,3264.69 1753.67,3264.69 1794.45,3264.69 1834.89,3264.69 1872.62,3264.69 1912.13,3265.37 1955.78,3265.37 3401.64,3366.28 3513.23,3366.28 3366.91,3367.14 3438.97,3367.14 3475.21,3367.14 3552.7,3367.14 3593.24,3368.84 3634.01,3368.84 3674.46,3368.84 3712.19,3368.84 3832.06,3368.84 3751.7,3369.51 3795.35,3369.51 3401.64,3403.48 3513.23,3403.48 3366.91,3404.34 3438.97,3404.34 3475.21,3404.34 3552.7,3404.34 3593.24,3406.04 3634.01,3406.04 3674.46,3406.04 3712.19,3406.04 3832.06,3406.04 3751.7,3406.72 3795.35,3406.72 3087.26,3532.67 3109,3533 2917.21,3767 2942.65,3767 2917.21,3789.86 2942.65,3789.86 3376.15,4830.83 2778.72,4904.67 3374.15,4913.03 2717.03,4978.7 2778.72,4985.11 3374.49,5053.88 2716.49,5056.16 3374,5129.97 440.11,5152.89
  other v2: 4673.68,1146.7 4650.06,1170.32 4673.68,1170.32 4697.3,1170.32 4673.68,1193.94 4673.68,1193.94 3052.24,1287.06 3008.93,1340.21 3052.24,1340.21 3095.54,1340.21 3008.93,1399.26 3052.24,1399.26 3095.54,1399.26 3052.24,1452.41 443.35,1562.61 486.65,1562.61 5152.35,1600.61 5195.65,1600.61 882.47,2857.32 858.85,2880.95 858.85,2880.95 882.47,2880.95 906.09,2880.95 906.09,2880.95 882.47,2904.57 4942.91,2911.23 4987,2911.23 5031.09,2911.23 4910.23,2943.91 4942.91,2943.91 4987,2943.91 5031.09,2943.91 5063.77,2943.91 4910.23,2988 4942.91,2988 4987,2988 5031.09,2988 5063.77,2988 4910.23,3032.09 4942.91,3032.09 4987,3032.09 5031.09,3032.09 5063.77,3032.09 4942.91,3064.77 4987,3064.77 5031.09,3064.77 4697.97,4609.75 4674.35,4633.37 4697.97,4633.37 4721.59,4633.37 4697.97,4656.99 4697.97,4656.99 3052.97,4887.77 3009.66,4940.92 3052.97,4940.92 3096.27,4940.92 3009.66,4999.97 3052.97,4999.97 3096.27,4999.97 5142.35,5011.61 5185.65,5011.61 3052.97,5053.12 418.35,5081.61 461.65,5081.61
GPIO0: R31.1 R110.2 U1.45 | length 431.5
  Top_SL w8: v1(4810.29,2944.28) 4812.59,2946.57 4820.01,2946.57 4821.1,2947.67 4862.84,2947.67 4863.74,2948.57 U1.45@4865.02,2948.57
  Signal_Layer w8: v1(4551.8,3028.68) 4554.78,3028.68 4615.94,2967.52 4656.35,2927.1 4722.34,2927.1 4722.58,2926.87 4788.57,2926.87 4797.56,2935.86 4802.8,2935.86 4810.29,2943.36 v1(4810.29,2944.28)
  Bottom_SL w8: R110.2@4551.61,3049.52 4551.71,3049.42 4551.71,3028.77 v1(4551.8,3028.68) 4551.8,3017.6 4552,3017.41 R31.1@4552,2983.08
GPIO1: R32.1 R118.2 U1.38 | length 546.9
  Top_SL w8: v1(4805.82,3081.24) 4808.11,3078.95 4817.53,3078.95 4837.67,3058.8 U1.38@4872.68,3058.8
  Signal_Layer w8: v1(4428.35,3022.39) 4489.38,3083.42 4803.64,3083.42 v1(4805.82,3081.24)
  Bottom_SL w8: R32.1@4428.35,2989.03 R118.2@4428.35,3056.16
GPIO2: R92.1 R128.2 U1.9 | length 1643.2
  Top_SL w10: U1.9@5026.37,2873.83 5027.12,2873.08 5027.12,2849.21 5035.33,2841 v3(5035.33,2839.38)
  Signal_Layer w8: v3(5035.33,2839.38) 5051.21,2823.5 5102.73,2823.5 5144.77,2781.46 5430.71,2781.46 5497,2847.75 v3(5497,3874.11)
  Bottom_SL w10: R92.1@5497,3839.49 v3(5497,3874.11) R128.2@5497,3905.06
GPIO3: R102.1 R129.2 U1.28 | length 914.8
  Top_SL w8: U1.28@5026.43,3109.98 5026.43,3120.65 5058.11,3152.33 5058.11,3171.53 v1(5060.41,3173.83)
  Signal_Layer w8: v1(4458.22,3020.39) 4458.22,3020.74 4496.6,3059.12 4753.66,3059.12 4794.71,3018.07 4892.35,3018.07 4897.17,3013.25 4994.8,3013.25 5012.25,3030.7 5012.25,3144.18 5025.93,3157.85 5044.43,3157.85 v1(5060.41,3173.83)
  Bottom_SL w8: R129.2@4458.22,2989.09 v1(4458.22,3020.39) R102.1@4458.22,3055.6
GPIO4: R130.1 R147.2 U1.2 | length 596.6
  Top_SL w8: v3(4882.02,2845.98) 4883.55,2847.51 4901.39,2847.51 4916.07,2862.19 4916.07,2866.02 4916.13,2866.08 U1.2@4916.13,2873.83
  Signal_Layer w8: v1(4515.6,3011.15) 4515.49,3011.04 4515.49,2971.8 4536,2951.29 4536,2921.13 4611.15,2845.98 v3(4882.02,2845.98)
  Bottom_SL w8: v1(4515.6,3011.15) 4517.7,3013.25 R130.1@4517.7,3052.82 ; v1@4516.97,3011.23 4516.97,2987.25 R147.2@4518.35,2985.87
GPIO5: R131.1 R148.2 U1.46 | length 506
  Top_SL w8: v1(4805.43,2916.86) 4808.68,2916.86 4814.08,2922.26 4815.15,2922.26 4825.77,2932.88 U1.46@4865.02,2932.88
  Signal_Layer w8: v1(4489.06,3021.47) 4500.49,3032.9 4520.71,3032.9 4639.51,2914.1 4716.61,2914.1 4716.85,2913.87 4793.95,2913.87 4794.65,2914.57 4803.14,2914.57 v1(4805.43,2916.86)
  Bottom_SL w8: R148.2@4487.22,2989.2 4488.14,2990.13 4488.14,3020.55 v1(4489.06,3021.47) 4489.06,3055.08 R131.1@4487.98,3056.16
GPIO6: R135.2 R136.1 U1.29 | length 1152.1
  Top_SL w8: U1.29@5010.69,3109.98 5010.69,3113.14 5011.63,3114.08 5011.63,3124.23 5041.41,3154.01 5041.41,3182.73 5041.41,3206.82 v1(5057.28,3222.7)
  Signal_Layer w8: v1(5057.28,3222.7) 5340.9,3222.7 5390.72,3272.51 v3(5390.72,3872.41)
  Bottom_SL w10: R136.1@5390.24,3839.49 5390.48,3839.73 v3@5390.48,3872.17 ; v3(5390.72,3872.41) v3@5390.48,3872.17 ; R135.2@5390.72,3905.06 5390.48,3904.82 v3@5390.48,3872.17
GPIO7: R137.1 R156.2 U1.27 U10.1 | length 1742.8
  Top_SL w8: U1.27@5042.18,3109.98 5042.18,3118.01 5081.34,3157.17 v1(5081.34,3203.7)
  Top_SL w10: v1(4946.78,4036.91) 4968.95,4036.91 U10.1@4987.4,4018.46
  Signal_Layer w10: v1(4946.78,4036.91) 4947.79,4035.91 4971.78,4035.91 4972.89,4034.8 4994.18,4034.8 5009.28,4049.91 5241.78,4049.91 v3(5419.28,3872.41) 5419.28,3274.3 5350.97,3206 5090.71,3206 5090.32,3205.61 5083.25,3205.61 v1(5081.34,3203.7)
  Bottom_SL w10: R137.1@5419.28,3839.49 5419.64,3839.85 v3@5419.64,3872.55 ; v3(5419.28,3872.41) 5420,3873.14 R156.2@5420,3905.06
GPIO8: R138.1 R158.2 U1.10 U25.1 | length 2410.6
  Top_SL w10: U1.10@5042.12,2873.83 5042.12,2868.08 5043.18,2867.02 5043.18,2857.12 5058.46,2841.84 5058.46,2811.33 v3(5084.26,2785.53) ; U25.1@5046.37,2134.44 5078.97,2134.44 5081.91,2131.5 5081.91,2122.1 v1(5083.82,2120.18)
  Signal_Layer w8: v1(5083.82,2120.18) 5100.02,2136.39 5103.38,2136.39 5103.38,2786.51 ; v3(5084.26,2785.53) 5085.23,2786.51 5103.38,2786.51 ; v3(5526.89,3874.11) 5526.89,2840.45 5454.91,2768.46 5139.39,2768.46 5121.34,2786.51 5103.38,2786.51
  Bottom_SL w10: R138.1@5526.89,3839.49 v3(5526.89,3874.11) R158.2@5526.89,3905.06
GPIO9: R165.1 R173.2 U1.8 | length 1634.3
  Top_SL w10: v3(5009.12,2845.48) 5009.87,2846.23 5009.87,2873.08 U1.8@5010.62,2873.83
  Signal_Layer w8: v3(5009.12,2845.48) 5011.28,2845.48 5022.18,2856.38 5088.24,2856.38 5150.16,2794.46 5408.34,2794.46 5473.59,2859.71 5473.59,3855.46 5464.66,3864.38 v3(5464.66,3874.11)
  Bottom_SL w10: R165.1@5464.64,3839.51 R173.2@5464.64,3905.04
I2C1_SCL: R3.2 R30.1 U1.42 U11.2 | length 4005.3
  Top_SL w8: v1(3189.36,542) 3211.85,542 ; U11.2@3211.85,497.53 3211.85,542 ; v1(3325.74,1096.67) 3323.45,1094.38 3323.45,1075.02 3211.85,963.43 3211.85,542 ; v1(3565.78,133.36) 3565.92,133.5 3565.92,183.98 R30.1@3566.07,184.13 ; v1(4805.57,2999.07) 4807.86,2996.77 4815.29,2996.77 4816.25,2995.81 U1.42@4872.68,2995.81
  Signal_Layer w8: v1(3325.74,1096.67) 3325.74,1308.94 4766.44,2749.64 4766.44,2752.53 v3(4836.26,2822.34)
  Bottom_SL w8: v1(3189.36,542) 3238.62,492.74 3238.62,432.54 3537.8,133.36 v1(3565.78,133.36) ; R3.2@4725.89,2983.87 4728.19,2981.57 4744.97,2981.57 4748.67,2977.87 4763.27,2977.87 4783.94,2998.53 4805.03,2998.53 v1(4805.57,2999.07) ; v1@4804.73,2998.53 4823.65,2979.61 4831.57,2979.61 4836.26,2974.93 v3(4836.26,2822.34)
I2C1_SDA: R4.2 R46.1 U1.40 U11.1 | length 4018.5
  Top_SL w8: U11.1@3231.54,497.53 3231.54,537.45 ; v1(3258.5,537.45) 3231.54,537.45 ; v1(3352.89,1096.67) 3350.6,1094.38 3350.6,1067.88 3231.54,948.82 3231.54,537.45 ; v1(3599.04,153.04) R46.1@3599.04,184.13 ; v1(4799.6,3040.04) 4801.9,3037.75 4816.36,3037.75 4826.73,3027.37 U1.40@4872.83,3027.37
  Signal_Layer w8: v1(3352.89,1096.67) 3352.89,1313.24 v3(4863.51,2823.85)
  Bottom_SL w8: v1(3258.5,537.45) 3258.5,435.25 3540.71,153.04 v1(3599.04,153.04) ; R4.2@4727.89,3040.87 4728.5,3040.25 v1@4798.59,3040.25 ; v1(4799.6,3040.04) 4799.4,3040.25 v1@4798.59,3040.25 ; v3(4863.51,2823.85) 4864.12,2824.46 4864.12,2981.85 4824.12,3021.84 4817,3021.84 v1@4798.59,3040.25
I2C2_IRQ: J11.5 R8.2 U1.39 | length 905
  Top_SL w8: J11.5@4506.44,3611.17 4602.3,3611.17 4666.32,3547.15 4666.32,3119.93 4722.98,3063.26 4774.07,3063.26 v1(4775.23,3064.42) 4777.41,3062.24 4810.24,3062.24 4828.96,3043.53 4846.78,3043.53 4847.19,3043.12 U1.39@4872.83,3043.12
  Bottom_SL w8: R8.2@4725.89,3068.87 4741.23,3068.87 4746.84,3063.26 4774.07,3063.26 v1(4775.23,3064.42)
I2C2_SCL: J11.3 R6.2 R45.2 U1.41 | length 3557.5
  Top_SL w8: J11.3@4506.44,3511.17 4608.06,3511.17 4634.5,3484.72 4634.5,3111.98 4728.64,3017.84 4768.07,3017.84 v1(4768.38,3017.53) 4794.47,3017.53 4795.01,3018.07 4815.56,3018.07 4822.01,3011.62 U1.41@4872.83,3011.62
  Top_SL w10: R45.2@3594,795.02 3594.17,795.19 3594.17,822.07 v1(3594.33,822.24)
  POWER w10: v1(3594.33,822.24) 3594.33,1749.07 4782.85,2937.58 4782.85,2954.15 4768.38,2968.62 v1(4768.38,3017.53)
  Bottom_SL w8: R6.2@4725.89,3012.87 4760.84,3012.87 4765.5,3017.53 v1(4768.38,3017.53)
I2C2_SDA: J11.1 R7.2 R47.2 U1.44 | length 3419.4
  Top_SL w8: J11.1@4506.44,3411.17 4580.14,3411.17 4611.15,3380.16 4611.15,3093.63 4683.88,3020.9 4687.82,3020.9 v1(4762.85,2945.87) ; v1@4765.15,2944.22 4783.37,2944.22 4803.52,2964.38 U1.44@4865.02,2964.38
  Top_SL w10: R47.2@3566,794.02 3566.04,794.06 3566.04,822.2 v1(3566.07,822.24)
  POWER w10: v1(3566.07,822.24) 3566.07,1749.09 v1(4762.85,2945.87)
  Bottom_SL w8: R7.2@4725.89,2926.87 4746.8,2926.87 4762.85,2942.92 v1(4762.85,2945.87)
I2C3_SCL: R9.2 R108.1 R144_USB1.2 R144_USB2.2 R150.2 R154.2 U2.6 U11.4 U18_V1.5 U18_V2.5 | length 8774.8
  Top_SL w8: v1(2844.01,4494.12) 2958.44,4494.12 2963.13,4498.81 2963.13,4757.8 R154.2@2963.31,4757.98 ; R150.2@2958.17,1136.71 2958.58,1136.31 2958.58,1107.2 v1(2958.98,1106.79) 2988.72,1077.06 v1(2988.72,906.12) 2988.72,885.88 3146.27,728.34 3146.27,529.42 3171.32,504.36 3172.42,504.36 3172.48,504.3 U11.4@3172.48,497.53 ; v3(3132.54,3450.16) U18_V1.5@3132.54,3485.01 ; U18_V2.5@3136.13,2307.58 3136.13,2302.3 3142.8,2295.63 v3(3142.8,2262.84) ; U2.6@4565.5,2755.52 4669.77,2755.52 4706.3,2792.06 4743.05,2792.06 v1(4745.35,2789.76) 4747.64,2792.06 4772.88,2792.06 R9.2@4775.18,2794.41 R9.2@4775.18,2794.41 4775.29,2794.3 4803.49,2794.3 R108.1@4803.6,2794.19
  Signal_Layer w8: v1(2958.98,1106.79) 2842.58,1223.2 2842.58,1631.1 3146.37,1934.89 3146.37,2096.79 3143.84,2099.32 v3@3143.84,2262.84 ; v3(3132.54,3450.16) 3132.54,2894.94 3156.18,2871.31 3156.18,2276.22 v3(3142.8,2262.84)
  Bottom_SL w8: R144_USB2.2@2797.98,931.89 2797.98,931.11 2822.97,906.12 v1(2988.72,906.12) ; R144_USB1.2@2841.98,4520.59 2844.01,4518.55 v1(2844.01,4494.12) 2844.01,4456.1 2884.79,4415.32 2927.33,4415.32 2994.94,4347.72 2994.94,4254.81 3270.91,3978.83 3270.91,3476.16 3244.92,3450.16 v3(3132.54,3450.16) ; v1(2903.47,4494.12) 3039.78,4357.82 3039.78,4268.14 3312.91,3995 3312.91,3446.2 3292.32,3425.61 3292.32,3064.68 3323,3034 4255.53,3034 4436.92,2852.6 4716.2,2852.6 4746.86,2821.94 4746.86,2791.28 v1(4745.35,2789.76)
I2C3_SDA: R10.2 R109.1 R145_USB1.2 R145_USB2.2 R151.2 U2.5 U11.3 U18_V1.6 U18_V2.6 U19.22 | length 7787.9
  Top_SL w8: R151.2@3011.8,1136.21 v1(3011.8,1107.54) v1@3011.8,929.45 ; v1(3012.87,930.52) v1@3011.8,929.45 ; v1(3013.24,4823.62) 3013.42,4823.8 3013.42,4856.1 U19.22@3013.6,4856.27 ; U18_V1.6@3152.23,3482.55 3152.23,3456.64 3162.67,3446.2 v3(3162.67,3421.74) ; U18_V2.6@3156.02,2314.55 3156.94,2313.63 3156.94,2290.23 3171.45,2275.71 v3(3173.17,2275.71) ; U11.3@3192.17,497.53 3192.17,504.3 3192.1,504.36 3192.1,507.27 3164.05,535.33 3164.05,752 3011.8,904.24 v1@3011.8,929.45 ; U2.5@4565.5,2705.52 4705.68,2705.52 4710.37,2710.21 v1(4710.37,2731.77) ; v1(4709.38,2826.98) 4712.63,2826.98 4724.57,2838.92 4746.7,2838.92 R10.2@4746.86,2839.08 ; R10.2@4746.85,2839.87 R109.1@4746.84,2869.87
  Signal_Layer w8: v1(2868.16,4467) 2979.95,4467 3013.24,4500.29 v1(3013.24,4823.62) ; v3(3162.67,3421.74) 3162.67,3419.58 3173.17,3409.08 v3(3173.17,2275.71) ; v1(4709.38,2826.98) 4709.87,2826.49 4709.87,2732.27 v1(4710.37,2731.77)
  Bottom_SL w8: R145_USB2.2@2825.96,932.28 2826.84,931.4 3011.99,931.4 v1(3012.87,930.52) ; R145_USB1.2@2869.98,4520.95 2869.98,4468.81 v1(2868.16,4467) 2897.5,4437.66 2932.1,4437.66 3018.12,4351.65 3018.12,4258.78 3293.01,3983.9 3293.01,3468.29 3246.46,3421.74 v3(3162.67,3421.74) ; v3@3161.67,3421.74 3161.67,2943.41 3318.57,2786.51 4668.91,2786.51 v1(4709.38,2826.98)
  Bottom_SL w10: v1(3011.8,1107.54) 3011.8,1178.12 2978.55,1211.37 2978.55,1485.38 2998.07,1504.89 2998.07,1810.96 3173.17,1986.07 v3(3173.17,2275.71) ; v1@3013.24,4821.86 v1(3013.24,4823.62)
ICD_TCK: J6.1 J6.4 R126.1 U36.49 U36.52 | length 870
  Top_SL w10: U36.52@3742.94,710.65 3742.94,882.53 J6.4@3746.52,886.12 3789.86,929.45 4003.19,929.45 J6.1@4046.52,886.12 4046.52,817.9 3939.28,710.65 U36.49@3802,710.65
ICD_TDI: J6.3 R125.1 U36.51 | length 210.2
  Top_SL w10: U36.51@3762.63,710.65 3762.63,734.86 3771.29,743.52 3771.29,810.88 J6.3@3846.52,886.12
ICD_TMS: J6.2 U36.50 | length 273.3
  Top_SL w10: U36.50@3782.39,730.26 3787.08,734.94 3787.08,736.52 3803.73,753.17 3888.12,753.17 3946.52,811.58 J6.2@3946.52,886.12
LDO_1V5: C9.2 U1.37 | length 93.2
  Top_SL w10: C9.2@4828.89,3130.59 C9.2@4827.45,3132.03 4827.45,3094.54 4847.38,3074.61 U1.37@4872.83,3074.61
LDO_3V3: C8.2 C12.1 R3.1 R4.1 R5.1 R6.1 R7.1 R8.1 R9.1 R10.1 R11.1 R13.2 R17.2 R18.2 R19.2 R22.2 U1.34 U2.8 | length 1620.9
  Top_SL w8: R10.1@4746.86,2817.82 4747.54,2817.14 R9.1@4774.5,2817.14
  Top_SL w10: R19.2@4234.71,2725.87 4234.71,2748.71 ; 4234.71,2758.32 4234.71,2748.71 ; 4234.98,2758.32 R18.2@4234.98,2777.52 ; R17.2@4235.19,2867.57 4235.98,2867.57 4237.28,2866.27 4237.28,2839.57 4243.14,2833.71 4400.15,2833.71 ; C12.1@4635.88,2855.09 4636.06,2855.27 C12.1@4636.06,2855.52 ; v1(4660.55,2895.1) 4637.96,2872.51 4637.96,2856.39 4637.1,2855.52 C12.1@4636.06,2855.52 ; R22.2@4872.81,3262 4891.51,3262 ; v1(4883.47,3176.99) 4883.47,3216.83 4891.51,3224.87 4891.51,3262 ; R13.2@4903.32,3263.57 4903.32,3263.3 4902.03,3262 4891.51,3262 ; v1(4926.5,3131.48) 4926.5,3128.77 4930.82,3124.45 4930.82,3103.24 U1.34@4931.88,3102.17 ; 4234.71,2748.71 4290.8,2748.71 4319.42,2777.33 4376.06,2777.33 4400.15,2801.41 4400.15,2833.71 ; 4400.15,2833.71 4526.96,2833.71 4548.77,2855.52 U2.8@4565.5,2855.52 C12.1@4636.06,2855.52
  Top_SL w15: R9.1@4774.5,2817.14 v1(4774.5,2826.98)
  Bottom_SL w10: v1(4660.55,2895.1) 4663.26,2895.1 4666.02,2897.87 4704.63,2897.87 4705.93,2896.57 4705.93,2890.3 4716.14,2880.08 4716.73,2880.08 4750.95,2845.86 4755.62,2845.86 v1(4774.5,2826.98) ; R11.1@4700.71,2897.87 4700.71,2926.87 4700.71,2955.87 4700.71,2983.87 4700.71,3040.87 4700.71,3144.97 4732.73,3176.99 v1(4883.47,3176.99) ; v1@4883.55,3177.07 C8.2@4915.12,3177.07 ; C8.2@4920.5,3176.44 4920.5,3140.18 4926.5,3134.19 v1(4926.5,3131.48)
MCU_I2C3_SCL: J13.1 R155.1 U11.7 | length 1471.4
  Top_SL w8: R155.1@3183.51,376.6 3184.81,377.89 3184.81,396.86 3187.56,399.61 3187.56,405.03 3192.17,409.63 U11.7@3192.17,444.38
  Signal_Layer w8: v1(3187.56,402.32) 3189.47,400.41 3242.45,400.41 3450.22,608.17 4163.52,608.17 4268.97,713.62 4268.97,822.24 4291.39,844.66 4317.65,844.66 J13.1@4332.85,859.86
MCU_I2C3_SDA: J14.1 R157.1 U11.8 | length 1249.4
  Top_SL w8: R157.1@3211.85,376.6 3212.17,376.91 v1(3212.17,420.41) 3211.91,420.66 3211.91,444.32 U11.8@3211.85,444.38
  Signal_Layer w8: v1(3212.17,420.41) 3213.6,420.41 3425.69,632.5 3934.2,632.5 4157.65,855.95 4206.15,855.95 J14.1@4211.08,860.88
MCU_VBUS: D19.2 D20.2 L7.1 TP12.1 | length 241.3
  Top_SL w10: D20.2@4307.86,178.34 4308.15,178.63 D19.2@4358.86,178.63 4409.28,178.63 L7.1@4410.17,179.52
  Top_SL w30: TP12.1@4187.94,133.36 4232.92,178.34 D20.2@4307.86,178.34
NetC37_2: C37.2 R29.1 U36.2 | length 127.5
  Top_SL w10: C37.2@3307.64,619.2 3307.64,619.39 3308.94,620.69 R29.1@3352.89,620.69 3356.44,617.15 U36.2@3432.9,617.15
NetC44_V1_1: C44_V1.1 U18_V1.22 | length 119.7
  Top_SL w10: C44_V1.1@2928.2,3547.51 U18_V1.22@3047.9,3547.51
NetC44_V1_2: C44_V1.2 L3_V1.1 Q3_V1.1 Q3_V1.2 Q3_V1.3 Q4_V1.5 Q4_V1.6 Q4_V1.7 Q4_V1.8 Q4_V1.9@2488.83,3358.01 U18_V1.23 | length 1204.5
  Top_SL w10: C44_V1.2@2928.2,3496.33 2929.19,3496.33 2948.87,3516.02 U18_V1.23@3049.37,3516.02
  Top_SL w15: 2847.75,3415.88 C44_V1.2@2928.2,3496.33
  Top_SL w30: Q4_V1.9@2488.83,3358.01 2546.71,3415.88 2847.75,3415.88
  Top_SL w50: Q3_V1.1@2379.29,3536 Q3_V1.2@2379.29,3586 ; Q3_V1.3@2379.29,3636 Q3_V1.2@2379.29,3586 ; Q4_V1.9@2488.83,3358.01 2488.83,3428.48 2488.83,3586 L3_V1.1@2488.83,3607.85 ; L3_V1.1@2488.83,3717.88 L3_V1.1@2488.83,3607.85 ; Q3_V1.2@2379.29,3586 2466.98,3586 L3_V1.1@2488.83,3607.85
NetC44_V2_1: C44_V2.1 U18_V2.22 | length 119.7
  Top_SL w10: C44_V2.1@2931.99,2379.51 U18_V2.22@3051.69,2379.51
NetC44_V2_2: C44_V2.2 L3_V2.1 Q3_V2.1 Q3_V2.2 Q3_V2.3 Q4_V2.5 Q4_V2.6 Q4_V2.7 Q4_V2.8 Q4_V2.9@2492.62,2190.01 U18_V2.23 | length 1195.9
  Top_SL w10: C44_V2.2@2931.99,2328.33 2932.98,2328.33 2952.66,2348.02 U18_V2.23@3053.16,2348.02
  Top_SL w15: 2754.45,2190.01 2892.78,2328.33 C44_V2.2@2931.99,2328.33
  Top_SL w30: Q4_V2.9@2492.66,2190.01 2754.45,2190.01
  Top_SL w50: Q3_V2.1@2383.08,2344 Q3_V2.2@2383.08,2394 ; Q3_V2.3@2383.08,2444 Q3_V2.2@2383.08,2394 ; L3_V2.1@2492.62,2395.16 2491.47,2394 Q3_V2.2@2383.08,2394 ; L3_V2.1@2492.62,2549.88 2492.66,2549.84 2492.66,2394.02 2492.66,2260.48 Q4_V2.9@2492.66,2190.01
NetC46_V1_1: C46_V1.1 U18_V1.20 | length 205.9
  Top_SL w10: C46_V1.1@2921.31,3719.88 2921.31,3673.41 2996.51,3598.21 3048.89,3598.21 U18_V1.20@3049.37,3598.69
NetC46_V1_2: C46_V1.2 L3_V1.2 U18_V1.21 U18_V1.25 | length 453.7
  Top_SL w10: L3_V1.2@2750.64,3717.88 L3_V1.2@2752.64,3719.88 ; C46_V1.2@2868.16,3719.88 2868.16,3679.99 2980.95,3567.2 U18_V1.21@3047.9,3567.2 3061.47,3567.2 3071.19,3557.47 3112.74,3557.47 U18_V1.25@3112.86,3557.36
  Top_SL w30: L3_V1.2@2752.64,3719.88 C46_V1.2@2868.16,3719.88
NetC46_V2_1: C46_V2.1 U18_V2.20 | length 205.9
  Top_SL w10: C46_V2.1@2925.1,2551.88 2925.1,2505.41 3000.3,2430.21 3052.68,2430.21 U18_V2.20@3053.16,2430.69
NetC46_V2_2: C46_V2.2 L3_V2.2 U18_V2.21 U18_V2.25 | length 453.7
  Top_SL w10: L3_V2.2@2754.43,2549.88 L3_V2.2@2756.43,2551.88 ; C46_V2.2@2871.95,2551.88 2871.95,2511.99 2984.74,2399.2 U18_V2.21@3051.69,2399.2 3065.26,2399.2 3074.98,2389.47 3116.53,2389.47 U18_V2.25@3116.65,2389.36
  Top_SL w30: L3_V2.2@2756.43,2551.88 C46_V2.2@2871.95,2551.88
NetC47_V1_1: C47_V1.1 C48_V1.1 C49_V1.1 C50_V1.1 C51_V1.1 C80_V1.2 R69_V1.1 R72_V1.2 U18_V1.11 U18_V1.26 | length 747.8
  Top_SL w10: U18_V1.26@3112.86,3581.96 C80_V1.2@3233.42,3581.96 ; R72_V1.2@3231.38,3816.43 3297.45,3816.43 R69_V1.1@3297.98,3815.9 ; C80_V1.2@3233.42,3584.91 3237.72,3589.22 3331.84,3589.22
  Top_SL w30: 3332.22,3588.84 3457.76,3588.84 ; 3457.96,3588.84 C49_V1.1@3527.59,3588.84 ; C49_V1.1@3527.69,3589.22 C51_V1.1@3792.69,3589.22
  other v1: 3088.19,3598.21 3110.77,3598.21 3133.47,3598.21
NetC47_V2_1: C47_V2.1 C48_V2.1 C49_V2.1 C50_V2.1 C51_V2.1 C80_V2.2 R69_V2.1 R72_V2.2 U18_V2.11 U18_V2.26 | length 732.8
  Top_SL w10: U18_V2.26@3116.65,2413.96 C80_V2.2@3244.39,2413.96 ; R72_V2.2@3235.17,2648.43 3301.24,2648.43 R69_V2.1@3301.77,2647.9
  Top_SL w30: C80_V2.2@3247,2416.57 3287.03,2416.57 3288.06,2415.55 3312.91,2415.55 3313.33,2415.97 C48_V2.1@3401.64,2415.97 3527.38,2415.97 C49_V2.1@3527.65,2415.7 3784.43,2415.7 C51_V2.1@3784.53,2415.59
  other v1: 3087.26,2430.87 3109.84,2430.87 3132.54,2430.87
NetC53_V1_1: C53_V1.1 R68_V1.1 R70_V1.2 U18_V1.4 | length 270.3
  Top_SL w10: R68_V1.1@3093.17,3285.96 R70_V1.2@3122.05,3285.96 ; U18_V1.4@3111.7,3486.32 3111.7,3387.3 3123.37,3375.63 3123.37,3287.26 R70_V1.2@3122.07,3285.96 ; C53_V1.1@3117.44,3252.17 3122.05,3256.78 R70_V1.2@3122.05,3285.96
NetC53_V2_1: C53_V2.1 R68_V2.1 R70_V2.2 U18_V2.4 | length 259.2
  Top_SL w10: R68_V2.1@3096.96,2117.96 R70_V2.2@3125.84,2117.96 ; U18_V2.4@3116.73,2307.74 3116.73,2300.5 3121.58,2295.64 3121.58,2258.61 3127.16,2253.03 3127.16,2119.26 R70_V2.2@3125.86,2117.96 ; C53_V2.1@3121.23,2084.17 3125.84,2088.78 R70_V2.2@3125.84,2117.96
NetC54_V1_1: C54_V1.1 R72_V1.1 U18_V1.12 | length 310.2
  Top_SL w10: U18_V1.12@3184.63,3601.73 3189.32,3606.41 3192.62,3606.41 3209.86,3623.65 R72_V1.1@3209.86,3815.9 ; R72_V1.1@3209.33,3816.43 3209.33,3870.18 3213.9,3874.75 C54_V1.1@3237.29,3874.75
NetC54_V1_2: C54_V1.2 R77_V1.1 U18_V1.13 | length 391.2
  Top_SL w10: U18_V1.13@3171.42,3630.19 3171.42,3899.26 3197.64,3925.48 R77_V1.1@3282.73,3925.48
NetC54_V2_1: C54_V2.1 R72_V2.1 U18_V2.12 | length 319.4
  Top_SL w10: U18_V2.12@3180.84,2433.49 3192.88,2433.49 3205.86,2446.48 3205.86,2641.17 3211.03,2646.34 3211.03,2647.13 3212.33,2648.43 R72_V2.1@3213.12,2648.43 3213.12,2702.18 3217.69,2706.75 C54_V2.1@3241.08,2706.75
NetC54_V2_2: C54_V2.2 R77_V2.1 U18_V2.13 | length 391.2
  Top_SL w10: U18_V2.13@3175.21,2462.19 3175.21,2731.26 3201.42,2757.48 R77_V2.1@3286.51,2757.48
NetC55_V1_2: C55_V1.2 U18_V1.7 | length 163
  Top_SL w10: U18_V1.7@3171.42,3484.52 3171.42,3476.31 3189.63,3458.1 C55_V1.2@3189.63,3329.07
NetC55_V2_2: C55_V2.2 U18_V2.7 | length 163
  Top_SL w10: U18_V2.7@3175.21,2316.52 3175.21,2308.31 3193.42,2290.1 C55_V2.2@3193.42,2161.07
NetC57_V1_1: C57_V1.1 R74_V1.2 U18_V1.18 | length 330.4
  Top_SL w10: C57_V1.1@3053.74,3953.2 3052.3,3951.76 R74_V1.2@3052.3,3882.51 3052.3,3683.52 3073.49,3662.33 U18_V1.18@3073.49,3632.16
NetC57_V2_1: C57_V2.1 R74_V2.2 U18_V2.18 | length 330.4
  Top_SL w10: C57_V2.1@3057.53,2785.2 3056.09,2783.76 R74_V2.2@3056.09,2714.51 3056.09,2515.52 3077.28,2494.33 U18_V2.18@3077.28,2464.16
NetC58_V1_1: C58_V1.1 R74_V1.1 | length 77.2
  Top_SL w10: C58_V1.1@3015.71,3953.2 3015.71,3896.26 3029.46,3882.51 R74_V1.1@3030.25,3882.51
NetC58_V2_1: C58_V2.1 R74_V2.1 | length 77.2
  Top_SL w10: C58_V2.1@3019.5,2785.2 3019.5,2728.26 3033.25,2714.51 R74_V2.1@3034.04,2714.51
NetC82_USB1_1: C82_USB1.1 C83_USB1.1 L4_USB1.2 U20_USB1.12 | length 136.4
  Bottom_SL w6: U20_USB1.12@2842.05,4643.27 2842.05,4708.68 C83_USB1.1@2846.99,4713.62 2846.99,4742.29 L4_USB1.2@2871.98,4767.27
NetC82_USB2_1: C82_USB2.1 C83_USB2.1 L4_USB2.2 U20_USB2.12 | length 126
  Bottom_SL w6: U20_USB2.12@2798.02,1054.61 C82_USB2.1@2797.98,1083.3 ; C82_USB2.1@2797.98,1083.3 2797.98,1121.56 C83_USB2.1@2800.53,1124.12 2800.53,1176.01 L4_USB2.2@2803,1178.47
NetC84_2: C84.2 R140.1 U19.26 | length 109.9
  Top_SL w6: C84.2@3060.84,4781.19 C84.2@3061.08,4780.95 ; R140.1@3089.37,4780.95 R140.1@3089.61,4780.71 3089.61,4796.8
  Top_SL w10: C84.2@3061.08,4780.95 R140.1@3089.37,4780.95 ; U19.26@3076.59,4856.27 3076.59,4809.82 3089.61,4796.8
NetC85_USB1_1: C85_USB1.1 U20_USB1.5 | length 42.6
  Bottom_SL w6.5: U20_USB1.5@2810.55,4584.21 2810.55,4564.31 2814,4560.86 C85_USB1.1@2814,4543.02
NetC85_USB2_1: C85_USB2.1 U20_USB2.5 | length 42.6
  Bottom_SL w6.5: U20_USB2.5@2766.56,995.52 2766.56,975.61 2770.01,972.16 C85_USB2.1@2770.01,954.33
NetC87_1: C87.1 U22.17 | length 61.7
  Top_SL w8: U22.17@898.22,2936.06 898.22,2982 908.82,2992.6 C87.1@909.61,2992.6
NetC87_2: C87.2 R14.2 | length 32.1
  Top_SL w10: R14.2@929.91,3023.72 929.91,2993.9 931.21,2992.6 C87.2@931.66,2992.6
NetC89_1: C89.1 R15.1 | length 42
  Top_SL w10: R15.1@907.48,2735.09 908.77,2736.39 910.67,2736.39 931.41,2757.13 931.41,2763.39 932.71,2764.69 C89.1@933.5,2764.69
NetC89_2: C89.2 U22.9 | length 67.1
  Top_SL w10: U22.9@898.22,2825.83 898.22,2777.14 910.66,2764.69 C89.2@911.45,2764.69
NetC99_1: C99.1 U22.13 | length 69
  Top_SL w10: U22.13@937.59,2880.95 C99.1@1006.61,2880.95
NetC100_USB1_1: C100_USB1.1 U20_USB1.11 | length 65.6
  Bottom_SL w6: C100_USB1.1@2811.27,4702.6 2811.27,4687.6 2826.3,4672.57 U20_USB1.11@2826.3,4643.27
NetC100_USB2_1: C100_USB2.1 U20_USB2.11 | length 65.6
  Bottom_SL w6: C100_USB2.1@2767.27,1113.9 2767.27,1113.12 2782.3,1098.08 U20_USB2.11@2782.3,1054.57
NetC104_2: C104.2 U5.4 | length 55.3
  Top_SL w10: C104.2@140.22,3274.31 140.71,3273.82 140.71,3219.91 U5.4@141.2,3219.42
NetC108_1: C108.1 C127.1 U36.25 | length 116.6
  Top_SL w10: C108.1@3631.33,182.08 C127.1@3660.86,182.08 3660.86,182.87 3664.2,186.21 U36.25@3664.2,267.74
NetC109_US1_1: C109_US1.1 C111_US1.1 C124_US1.1 C125_US1.1 C126_US1.1 D14_US1.1 J8_US1.A4 J8_US1.A9 J8_US1.B4 J8_US1.B9 L5_US1.1 U24_US1.4 U24_US1.5 U24_US1.6 | length 984.5
  Top_SL w30: v1(404.6,4921.94) 404.6,5031.2 414.41,5041 465.59,5041 C109_US1.1@599,5041 ; v1(408.14,4679.25) 409.1,4678.29 409.1,4607.01 C124_US1.1@410.3,4605.81 446.54,4605.81 454.8,4597.54 454.8,4524.53 L5_US1.1@448.8,4518.53
  POWER w25: v1@403.65,4920.98 381.35,4920.98 322.91,4862.54 322.91,4844.4 316.33,4837.82 316.33,4837.36 J8_US1.B4@316.22,4837.24 316.33,4837.13 327.68,4837.13 346.52,4818.3 346.52,4761.7 327.68,4742.87 316.33,4742.87 J8_US1.B9@316.22,4742.76 379.73,4679.25 v1(408.14,4679.25)
  Bottom_SL w12: J8_US1.B9@316.22,4742.76 318.19,4740.79 J8_US1.A4@359.92,4740.79 ; J8_US1.B4@316.33,4837.24 318.01,4838.92 J8_US1.A9@359.92,4838.92
  Bottom_SL w15: J8_US1.B4@316.22,4837.24 J8_US1.B4@316.33,4837.24
NetC109_US2_1: C109_US2.1 C111_US2.1 C124_US2.1 C125_US2.1 C126_US2.1 D14_US2.1 J8_US2.A4 J8_US2.A9 J8_US2.B4 J8_US2.B9 L5_US2.1 U24_US2.4 U24_US2.5 U24_US2.6 | length 986.2
  Top_SL w30: C124_US2.1@413.9,1101.99 442.54,1101.99 467.85,1076.68 467.85,1023.38 L5_US2.1@473.7,1017.53 ; v1(413.9,1185.73) 413.9,1103.47 C124_US2.1@414.39,1102.99 ; v1(414.18,1414.08) 414.18,1496.14 439.44,1521.4 465.03,1521.4 490.63,1521.4 C126_US2.1@533.75,1521.4 ; C126_US2.1@540,1520.32 C125_US2.1@582,1520.32 C109_US2.1@632.13,1520.32
  POWER w25: v1(413.9,1185.73) 377.24,1185.73 J8_US2.B9@316.22,1246.76 316.33,1246.87 327.68,1246.87 346.52,1265.7 346.52,1322.3 327.68,1341.13 316.33,1341.13 J8_US2.B4@316.22,1341.24 389.06,1414.08 v1(414.18,1414.08)
  Bottom_SL w15: J8_US2.B9@316.22,1246.76 317.89,1245.08 359.63,1245.08 J8_US2.A4@359.92,1244.79 ; J8_US2.B4@316.22,1341.24 317.89,1342.92 359.63,1342.92 J8_US2.A9@359.92,1343.21
NetC110_1: C110.1 C128.1 U36.56 | length 97.1
  Top_SL w10: C110.1@3622,773.98 3622.07,773.91 3649.96,773.91 C128.1@3650.03,773.84 3650.03,767.34 3664.2,753.17 U36.56@3664.2,710.65
NetC113_1: C113.1 U36.40 Y1.1 | length 276.4
  Top_SL w8: U36.40@3875.82,479.35 3939.28,479.35 3952.27,466.36 C113.1@3996.52,466.36 4100.8,466.36 4107.5,459.67 Y1.1@4107.5,423.05
NetC114_1: C114.1 U36.41 Y1.3 | length 176.8
  Top_SL w8: U36.41@3875.82,499.04 3937.4,499.04 3940.75,495.69 3996.45,495.69 C114.1@3996.52,495.62 4030.46,495.62 Y1.3@4044.5,509.67
  Top_SL w10: U36.41@3875.82,499.04 U36.41@3876.4,498.45
NetC115_2: C115.2 J7.1 L7.2 | length 225.8
  Top_SL w10: L7.2@4410.17,234.64 4410.28,234.52 C115.2@4455.86,234.52 4586.18,234.52 4608.14,212.56 J7.1@4608.14,193.86
NetC123_DS1_2: C123_DS1.2 U23_DS1.3 | length 68.8
  Top_SL w6.5: U23_DS1.3@4697.97,4688.29 C123_DS1.2@4697.97,4757.06
NetC123_DS2_2: C123_DS2.2 U23_DS2.3 | length 42.1
  Top_SL w6.5: U23_DS2.3@4673.68,1225.44 C123_DS2.2@4673.68,1267.58
NetC129_2: C129.2 R132.1 R133.1 R146.1 U1.3 | length 267.3
  Top_SL w10: R133.1@4773.08,2749.42 R146.1@4805.82,2749.43 4812.12,2749.42 4812.31,2749.22 4837.1,2749.22 R132.1@4837.31,2749.01 C129.2@4902.3,2749.01 ; C129.2@4902.53,2748.03 4902.53,2825.53 4931.88,2854.88 U1.3@4931.88,2873.83
NetC130_2: C130.2 R164.2 | length 37.6
  Top_SL w10: C130.2@5134.38,3922.59 R164.2@5134.38,3960.2
NetC131_2: C131.2 R172.2 | length 36.5
  Top_SL w8: R172.2@4896.49,2189.07 4896.83,2189.4 4896.83,2224.92 C131.2@4897.17,2225.26
NetD1_2: D1.2 R1.2 | length 40.7
  Top_SL w10: D1.2@4987.33,3799.18 4988.71,3800.56 R1.2@5027.49,3800.56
